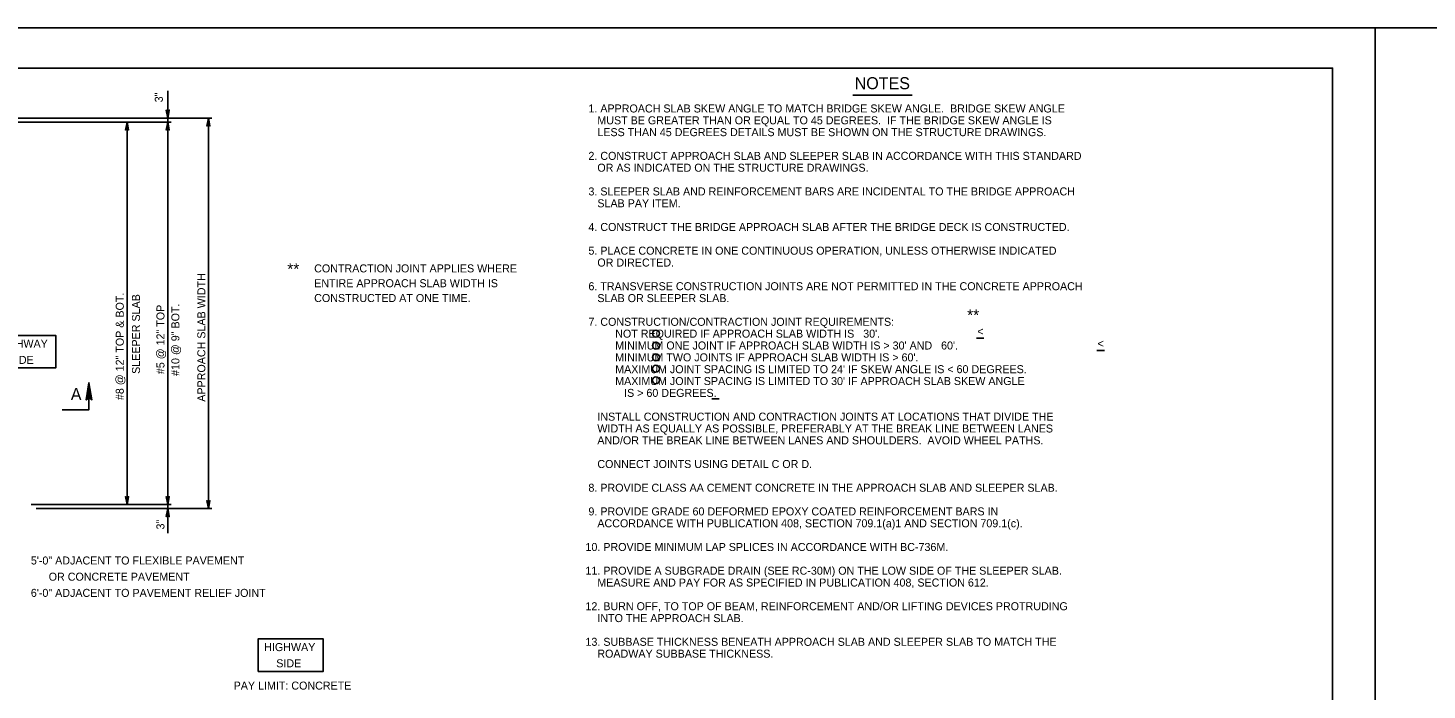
# Model space of a CAD drawing. Extents: x 638079 to 640019, y 297691 to 298879.
# Drawn here: x 638610 to 639134, y 298631 to 298879 of the extents above; entities that cross this region are included whole.
import ezdxf

# ---------------------------------------------------------------- set-up
doc = ezdxf.new("R2010")
doc.units = 0
doc.layers.add('1', color=7, linetype='Continuous')
doc.layers.add('PLT-BNDY', color=7, linetype='Continuous')

msp = doc.modelspace()

# ---------------------------------------------------------------- linework, layer by layer
at = {"layer": '1'}
for p, q in [((639115.03, 298879.23), (639115.03, 298879.23)), ((638662.52, 298689.95), (638662.52, 298855.62)), ((638919.3, 298854.02), (638941.48, 298854.02)), ((638558.6, 298845.46), (638679.01, 298845.46)), ((638559.41, 298843.93), (638663.72, 298843.93)), ((638647.28, 298700.68), (638647.28, 298843.93)), ((638677.76, 298699.15), (638677.76, 298845.46)), ((638965.56, 298762.97), (638968.35, 298762.97)), ((639010.72, 298758.41), (639013.51, 298758.41)), ((638866.35, 298740.29), (638869.15, 298740.29)), ((638611.33, 298700.68), (638663.72, 298700.68)), ((638613.23, 298699.15), (638679.01, 298699.15))]:
    msp.add_line(p, q, dxfattribs=at)
for points in [[(639099.03, 298300.23), (639099.03, 298864.23), (638313.03, 298864.23), (638313.03, 298300.23), (639099.03, 298300.23), (639099.03, 298326.59), (638899.03, 298326.59), (638899.03, 298391.26), (639099.03, 298391.26), (639099.03, 298420.23), (638899.03, 298420.23), (638899.03, 298300.23), (638977.83, 298300.23), (638977.83, 298326.59), (638977.83, 298300.23), (639054.83, 298300.23), (639054.83, 298326.59), (639054.83, 298314.27), (639099.03, 298314.27)], [(638662.52, 298845.46), (638661.96, 298848.44), (638662.04, 298848.33), (638662.12, 298848.21), (638662.22, 298848.15), (638662.32, 298848.09), (638662.42, 298848.07), (638662.52, 298848.06), (638662.62, 298848.07), (638662.72, 298848.09), (638662.82, 298848.15), (638662.92, 298848.21), (638663, 298848.33), (638663.08, 298848.44), (638662.52, 298845.46), (638663, 298848.33), (638662.92, 298848.21), (638662.52, 298845.46), (638662.82, 298848.15), (638662.72, 298848.09), (638662.52, 298845.46), (638662.62, 298848.07), (638662.52, 298848.06), (638662.52, 298845.46), (638662.42, 298848.07), (638662.32, 298848.09), (638662.52, 298845.46), (638662.22, 298848.15), (638662.12, 298848.21), (638662.52, 298845.46), (638662.04, 298848.33)], [(638647.28, 298843.93), (638647.84, 298840.95), (638647.76, 298841.07), (638647.68, 298841.18), (638647.58, 298841.24), (638647.48, 298841.3), (638647.38, 298841.32), (638647.28, 298841.33), (638647.18, 298841.32), (638647.08, 298841.3), (638646.98, 298841.24), (638646.88, 298841.18), (638646.8, 298841.07), (638646.72, 298840.95), (638647.28, 298843.93), (638646.8, 298841.07), (638646.88, 298841.18), (638647.28, 298843.93), (638646.98, 298841.24), (638647.08, 298841.3), (638647.28, 298843.93), (638647.18, 298841.32), (638647.28, 298841.33), (638647.28, 298843.93), (638647.38, 298841.32), (638647.48, 298841.3), (638647.28, 298843.93), (638647.58, 298841.24), (638647.68, 298841.18), (638647.28, 298843.93), (638647.76, 298841.07)], [(638662.52, 298843.93), (638663.08, 298840.95), (638663, 298841.07), (638662.92, 298841.18), (638662.82, 298841.24), (638662.72, 298841.3), (638662.62, 298841.32), (638662.52, 298841.33), (638662.42, 298841.32), (638662.32, 298841.3), (638662.22, 298841.24), (638662.12, 298841.18), (638662.04, 298841.07), (638661.96, 298840.95), (638662.52, 298843.93), (638662.04, 298841.07), (638662.12, 298841.18), (638662.52, 298843.93), (638662.22, 298841.24), (638662.32, 298841.3), (638662.52, 298843.93), (638662.42, 298841.32), (638662.52, 298841.33), (638662.52, 298843.93), (638662.62, 298841.32), (638662.72, 298841.3), (638662.52, 298843.93), (638662.82, 298841.24), (638662.92, 298841.18), (638662.52, 298843.93), (638663, 298841.07)], [(638677.76, 298845.46), (638678.32, 298842.47), (638678.24, 298842.59), (638678.16, 298842.7), (638678.06, 298842.76), (638677.96, 298842.82), (638677.86, 298842.84), (638677.76, 298842.86), (638677.66, 298842.84), (638677.56, 298842.82), (638677.46, 298842.76), (638677.36, 298842.7), (638677.28, 298842.59), (638677.2, 298842.47), (638677.76, 298845.46), (638677.28, 298842.59), (638677.36, 298842.7), (638677.76, 298845.46), (638677.46, 298842.76), (638677.56, 298842.82), (638677.76, 298845.46), (638677.66, 298842.84), (638677.76, 298842.86), (638677.76, 298845.46), (638677.86, 298842.84), (638677.96, 298842.82), (638677.76, 298845.46), (638678.06, 298842.76), (638678.16, 298842.7), (638677.76, 298845.46), (638678.24, 298842.59)], [(638622.88, 298736.2), (638632.96, 298736.2), (638632.96, 298746.28)], [(638633.73, 298740.17), (638633.29, 298740.4), (638632.96, 298746.28), (638633.73, 298740.17), (638633.99, 298739.86), (638632.96, 298746.28), (638632.67, 298740.4), (638632.23, 298740.19), (638632.96, 298746.28), (638631.94, 298739.86), (638632.23, 298740.19)], [(638647.28, 298700.68), (638646.72, 298703.66), (638646.8, 298703.55), (638646.88, 298703.43), (638646.98, 298703.37), (638647.08, 298703.31), (638647.18, 298703.29), (638647.28, 298703.28), (638647.38, 298703.29), (638647.48, 298703.31), (638647.58, 298703.37), (638647.68, 298703.43), (638647.76, 298703.55), (638647.84, 298703.66), (638647.28, 298700.68), (638647.76, 298703.55), (638647.68, 298703.43), (638647.28, 298700.68), (638647.58, 298703.37), (638647.48, 298703.31), (638647.28, 298700.68), (638647.38, 298703.29), (638647.28, 298703.28), (638647.28, 298700.68), (638647.18, 298703.29), (638647.08, 298703.31), (638647.28, 298700.68), (638646.98, 298703.37), (638646.88, 298703.43), (638647.28, 298700.68), (638646.8, 298703.55)], [(638662.52, 298700.68), (638661.96, 298703.66), (638662.04, 298703.55), (638662.12, 298703.43), (638662.22, 298703.37), (638662.32, 298703.31), (638662.42, 298703.29), (638662.52, 298703.28), (638662.62, 298703.29), (638662.72, 298703.31), (638662.82, 298703.37), (638662.92, 298703.43), (638663, 298703.55), (638663.08, 298703.66), (638662.52, 298700.68), (638663, 298703.55), (638662.92, 298703.43), (638662.52, 298700.68), (638662.82, 298703.37), (638662.72, 298703.31), (638662.52, 298700.68), (638662.62, 298703.29), (638662.52, 298703.28), (638662.52, 298700.68), (638662.42, 298703.29), (638662.32, 298703.31), (638662.52, 298700.68), (638662.22, 298703.37), (638662.12, 298703.43), (638662.52, 298700.68), (638662.04, 298703.55)], [(638677.76, 298699.15), (638677.2, 298702.14), (638677.28, 298702.02), (638677.36, 298701.91), (638677.46, 298701.85), (638677.56, 298701.79), (638677.66, 298701.77), (638677.76, 298701.75), (638677.86, 298701.77), (638677.96, 298701.79), (638678.06, 298701.85), (638678.16, 298701.91), (638678.24, 298702.02), (638678.32, 298702.14), (638677.76, 298699.15), (638678.24, 298702.02), (638678.16, 298701.91), (638677.76, 298699.15), (638678.06, 298701.85), (638677.96, 298701.79), (638677.76, 298699.15), (638677.86, 298701.77), (638677.76, 298701.75), (638677.76, 298699.15), (638677.66, 298701.77), (638677.56, 298701.79), (638677.76, 298699.15), (638677.46, 298701.85), (638677.36, 298701.91), (638677.76, 298699.15), (638677.28, 298702.02)], [(638662.52, 298699.15), (638663.08, 298696.17), (638663, 298696.29), (638662.92, 298696.4), (638662.82, 298696.46), (638662.72, 298696.52), (638662.62, 298696.54), (638662.52, 298696.55), (638662.42, 298696.54), (638662.32, 298696.52), (638662.22, 298696.46), (638662.12, 298696.4), (638662.04, 298696.29), (638661.96, 298696.17), (638662.52, 298699.15), (638662.04, 298696.29), (638662.12, 298696.4), (638662.52, 298699.15), (638662.22, 298696.46), (638662.32, 298696.52), (638662.52, 298699.15), (638662.42, 298696.54), (638662.52, 298696.55), (638662.52, 298699.15), (638662.62, 298696.54), (638662.72, 298696.52), (638662.52, 298699.15), (638662.82, 298696.46), (638662.92, 298696.4), (638662.52, 298699.15), (638663, 298696.29)]]:
    msp.add_lwpolyline(points, dxfattribs=at)
for points in [[(638596.11, 298751.82), (638620.5, 298751.82), (638620.5, 298764.01), (638596.11, 298764.01)], [(638696.37, 298638.13), (638720.76, 298638.13), (638720.76, 298650.32), (638696.37, 298650.32)]]:
    msp.add_lwpolyline(points, close=True, dxfattribs=at)
for centre in [(638845.45, 298764.73), (638845.45, 298760.21), (638845.45, 298755.82), (638845.45, 298751.56), (638845.45, 298747.2)]:
    msp.add_circle(centre, 1.3, dxfattribs=at)
at = {"layer": 'PLT-BNDY'}
for points in [[(638274.03, 298879.23), (639115.03, 298879.23), (639115.03, 298285.23), (638274.03, 298285.23)], [(639115.03, 298879.23), (639956.03, 298879.23), (639956.03, 298285.23), (639115.03, 298285.23)]]:
    msp.add_lwpolyline(points, close=True, dxfattribs=at)

# ---------------------------------------------------------------- texts
at = {"layer": '1'}
for s, height, p in [('NOTES', 4.5, (638919.92, 298856.29)), (' 1. APPROACH SLAB SKEW ANGLE TO MATCH BRIDGE SKEW ANGLE.  BRIDGE SKEW ANGLE', 3, (638819.04, 298847.57)), ('    MUST BE GREATER THAN OR EQUAL TO 45 DEGREES.  IF THE BRIDGE SKEW ANGLE IS', 3, (638819.04, 298843.13)), ('    LESS THAN 45 DEGREES DETAILS MUST BE SHOWN ON THE STRUCTURE DRAWINGS.', 3, (638819.04, 298838.69)), (' 2. CONSTRUCT APPROACH SLAB AND SLEEPER SLAB IN ACCORDANCE WITH THIS STANDARD', 3, (638819.04, 298829.81)), ('    OR AS INDICATED ON THE STRUCTURE DRAWINGS.', 3, (638819.04, 298825.37)), (' 3. SLEEPER SLAB AND REINFORCEMENT BARS ARE INCIDENTAL TO THE BRIDGE APPROACH', 3, (638819.04, 298816.48)), ('    SLAB PAY ITEM.', 3, (638819.04, 298812.04)), (' 4. CONSTRUCT THE BRIDGE APPROACH SLAB AFTER THE BRIDGE DECK IS CONSTRUCTED.', 3, (638819.04, 298803.16)), (' 5. PLACE CONCRETE IN ONE CONTINUOUS OPERATION, UNLESS OTHERWISE INDICATED', 3, (638819.04, 298794.28)), ('**', 4.32, (638707.29, 298786.77)), ('CONTRACTION JOINT APPLIES WHERE', 3, (638717.37, 298787.64)), ('    OR DIRECTED.', 3, (638819.04, 298789.84)), ('ENTIRE APPROACH SLAB WIDTH IS', 3, (638717.37, 298782.09)), (' 6. TRANSVERSE CONSTRUCTION JOINTS ARE NOT PERMITTED IN THE CONCRETE APPROACH', 3, (638819.04, 298780.96)), ('CONSTRUCTED AT ONE TIME.', 3, (638717.37, 298776.54)), ('    SLAB OR SLEEPER SLAB.', 3, (638819.04, 298776.51)), ('**', 4.32, (638962.11, 298769.48)), (' 7. CONSTRUCTION/CONTRACTION JOINT REQUIREMENTS:', 3, (638819.04, 298767.63)), ("          NOT REQUIRED IF APPROACH SLAB WIDTH IS   30'.", 3, (638819.04, 298763.19)), ('<', 3, (638965.91, 298764.06)), ('HIGHWAY', 3, (638598.38, 298759.43)), ("          MINIMUM ONE JOINT IF APPROACH SLAB WIDTH IS > 30' AND   60'.", 3, (638819.04, 298758.75)), ('<', 3, (639010.97, 298759.5)), ('SIDE', 3, (638602.9, 298753.36)), ("          MINIMUM TWO JOINTS IF APPROACH SLAB WIDTH IS > 60'.", 3, (638819.04, 298754.31)), ("          MAXIMUM JOINT SPACING IS LIMITED TO 24' IF SKEW ANGLE IS < 60 DEGREES.", 3, (638819.04, 298749.87)), ("          MAXIMUM JOINT SPACING IS LIMITED TO 30' IF APPROACH SLAB SKEW ANGLE ", 3, (638819.04, 298745.43)), ('A', 4.5, (638626.16, 298739.78)), ('             IS > 60 DEGREES.', 3, (638819.04, 298740.99)), ('    INSTALL CONSTRUCTION AND CONTRACTION JOINTS AT LOCATIONS THAT DIVIDE THE', 3, (638819.04, 298732.1)), ('    AND/OR THE BREAK LINE BETWEEN LANES AND SHOULDERS.  AVOID WHEEL PATHS.', 3, (638819.04, 298723.22)), ('    WIDTH AS EQUALLY AS POSSIBLE, PREFERABLY AT THE BREAK LINE BETWEEN LANES', 3, (638819.04, 298727.66)), ('    CONNECT JOINTS USING DETAIL C OR D.', 3, (638819.04, 298714.34)), (' 8. PROVIDE CLASS AA CEMENT CONCRETE IN THE APPROACH SLAB AND SLEEPER SLAB.', 3, (638819.04, 298705.46)), (' 9. PROVIDE GRADE 60 DEFORMED EPOXY COATED REINFORCEMENT BARS IN', 3, (638819.04, 298696.58)), ('    ACCORDANCE WITH PUBLICATION 408, SECTION 709.1(a)1 AND SECTION 709.1(c).', 3, (638819.04, 298692.13)), ('10. PROVIDE MINIMUM LAP SPLICES IN ACCORDANCE WITH BC-736M.', 3, (638819.04, 298683.25)), ('5\'-0" ADJACENT TO FLEXIBLE PAVEMENT', 3, (638611.19, 298678.19)), ('      OR CONCRETE PAVEMENT', 3, (638611.19, 298672.12)), ('11. PROVIDE A SUBGRADE DRAIN (SEE RC-30M) ON THE LOW SIDE OF THE SLEEPER SLAB.', 3, (638819.04, 298674.37)), ('6\'-0" ADJACENT TO PAVEMENT RELIEF JOINT', 3, (638611.19, 298666.05)), ('    MEASURE AND PAY FOR AS SPECIFIED IN PUBLICATION 408, SECTION 612.', 3, (638819.04, 298669.93)), ('12. BURN OFF, TO TOP OF BEAM, REINFORCEMENT AND/OR LIFTING DEVICES PROTRUDING', 3, (638819.04, 298661.05)), ('    INTO THE APPROACH SLAB.', 3, (638819.04, 298656.61)), ('HIGHWAY', 3, (638698.64, 298645.74)), ('13. SUBBASE THICKNESS BENEATH APPROACH SLAB AND SLEEPER SLAB TO MATCH THE', 3, (638819.04, 298647.72)), ('SIDE', 3, (638703.16, 298639.67)), ('    ROADWAY SUBBASE THICKNESS.', 3, (638819.04, 298643.28)), ('PAY LIMIT: CONCRETE', 3, (638687.19, 298631.31))]:
    msp.add_text(s, height=height, dxfattribs=at).set_placement(p)
for s, p in [('3"', (638660.64, 298851.37)), ('APPROACH SLAB WIDTH', (638676.58, 298739.18)), ('#8 @ 12" TOP & BOT.', (638646.01, 298739.79)), ('SLEEPER SLAB', (638652.08, 298749.61)), ('#5 @ 12" TOP', (638661.26, 298749.51)), ('#10 @ 9" BOT.', (638666.85, 298748.85)), ('3"', (638661.25, 298691.3))]:
    msp.add_text(s, height=3, rotation=90, dxfattribs=at).set_placement(p)

doc.saveas('drawing.dxf')
